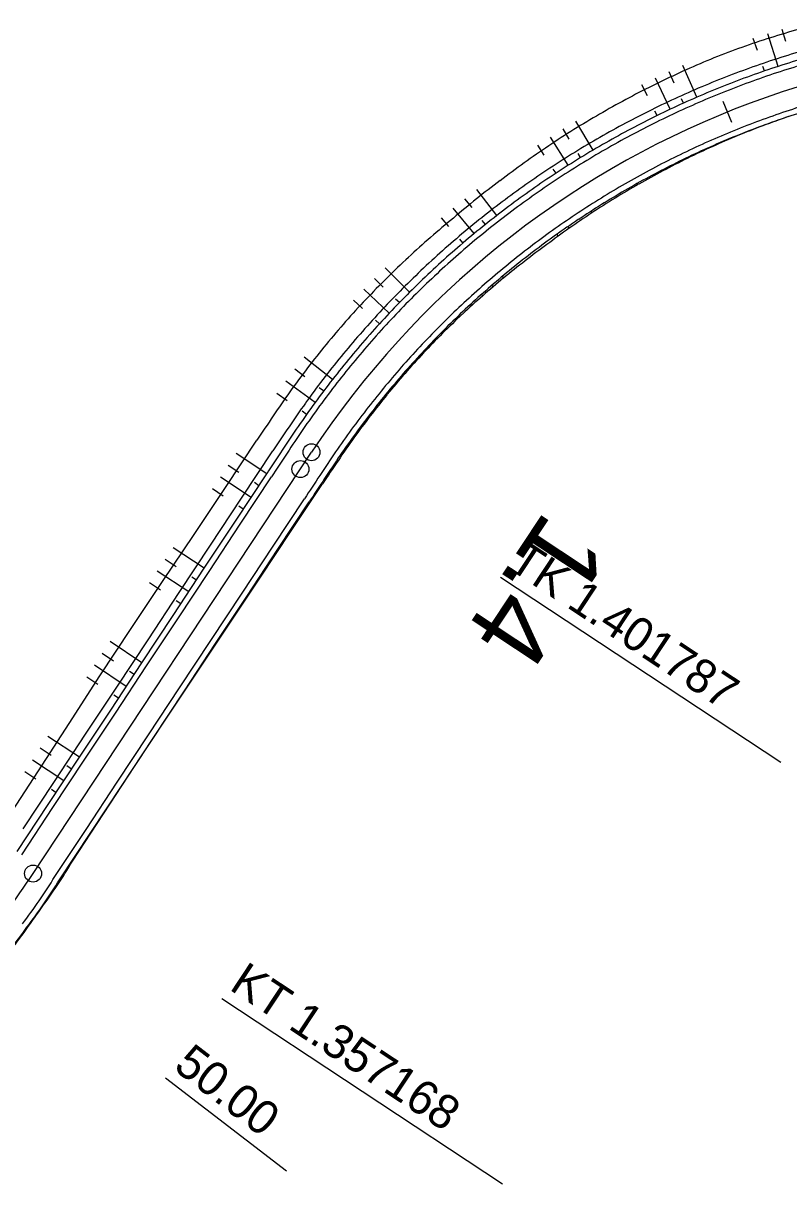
# Model space of a CAD drawing. Extents: x -481656 to -478728, y -1113199 to -1110710.
# Drawn here: x -478987.9 to -478920.3, y -1110817.8 to -1110715.2 of the extents above; entities that cross this region are included whole.
import ezdxf

# ---------------------------------------------------------------- set-up
doc = ezdxf.new("R2010")
doc.units = 0
for name, color, linetype in [('C5_HATCH_SLOPE_L', 7, 'Continuous'), ('C5_HATCH_SLOPE_R', 7, 'Continuous'), ('C5_HECTOMETRY', 7, 'Continuous'), ('C5_HLBODY', 7, 'Continuous'), ('C5_HRANA_TELESO', 7, 'Continuous'), ('C5_KORUNA', 7, 'Continuous'), ('C5_OSA', 7, 'Continuous'), ('C5_PRIKOP', 7, 'Continuous'), ('C5_STANICENI', 7, 'Continuous'), ('C5_ZPEVKRAJ', 7, 'Continuous')]:
    doc.layers.add(name, color=color, linetype=linetype)

msp = doc.modelspace()

# ---------------------------------------------------------------- linework, layer by layer
at = {"layer": 'C5_HATCH_SLOPE_L'}
for p, q in [((-478920.56, -1110716.84), (-478920.89, -1110715.79)), ((-478923.07, -1110717.64), (-478923.43, -1110716.58)), ((-478921.23, -1110719.05), (-478922.16, -1110716.18)), ((-478928.43, -1110721.78), (-478929.65, -1110718.97)), ((-478922.44, -1110719.45), (-478922.58, -1110719.07)), ((-478930.78, -1110722.84), (-478932.07, -1110720.09)), ((-478930.41, -1110720.53), (-478930.86, -1110719.52)), ((-478932.78, -1110721.66), (-478933.27, -1110720.68)), ((-478929.61, -1110722.3), (-478929.78, -1110721.92)), ((-478931.93, -1110723.39), (-478932.12, -1110723.02)), ((-478937.59, -1110726.45), (-478939.1, -1110723.88)), ((-478939.69, -1110725.48), (-478940.24, -1110724.58)), ((-478941.9, -1110726.89), (-478942.47, -1110726.02)), ((-478939.78, -1110727.79), (-478941.36, -1110725.29)), ((-478938.69, -1110727.11), (-478938.91, -1110726.74)), ((-478940.86, -1110728.49), (-478941.1, -1110728.12)), ((-478946.09, -1110732.22), (-478947.86, -1110729.92)), ((-478948.28, -1110731.53), (-478948.91, -1110730.74)), ((-478948.09, -1110733.82), (-478949.95, -1110731.58)), ((-478950.32, -1110733.2), (-478950.97, -1110732.43)), ((-478947.1, -1110733.01), (-478947.37, -1110732.66)), ((-478949.08, -1110734.65), (-478949.37, -1110734.31)), ((-478953.8, -1110739.01), (-478955.94, -1110736.86)), ((-478956.13, -1110738.54), (-478956.89, -1110737.79)), ((-478955.59, -1110740.85), (-478957.83, -1110738.74)), ((-478957.95, -1110740.43), (-478958.76, -1110739.7)), ((-478954.7, -1110739.92), (-478955.03, -1110739.6)), ((-478956.46, -1110741.79), (-478956.81, -1110741.48)), ((-478960.61, -1110746.7), (-478963.11, -1110744.75)), ((-478963.04, -1110746.48), (-478963.93, -1110745.8)), ((-478962.15, -1110748.75), (-478964.73, -1110746.87)), ((-478961.39, -1110747.72), (-478961.77, -1110747.44)), ((-478964.6, -1110748.6), (-478965.52, -1110747.95)), ((-478962.9, -1110749.8), (-478963.29, -1110749.52)), ((-478966.42, -1110755.05), (-478969.12, -1110753.26)), ((-478968.87, -1110754.93), (-478969.82, -1110754.3)), ((-478967.8, -1110757.14), (-478970.51, -1110755.34)), ((-478967.11, -1110756.09), (-478967.51, -1110755.82)), ((-478970.25, -1110757.01), (-478971.21, -1110756.38)), ((-478968.49, -1110758.18), (-478968.89, -1110757.91)), ((-478971.93, -1110763.39), (-478974.69, -1110761.57)), ((-478974.41, -1110763.25), (-478975.39, -1110762.61)), ((-478973.31, -1110765.48), (-478976.08, -1110763.65)), ((-478972.62, -1110764.44), (-478973.03, -1110764.17)), ((-478975.8, -1110765.33), (-478976.78, -1110764.68)), ((-478974, -1110766.52), (-478974.41, -1110766.25)), ((-478977.44, -1110771.74), (-478980.26, -1110769.87)), ((-478979.95, -1110771.58), (-478980.95, -1110770.92)), ((-478978.82, -1110773.82), (-478981.64, -1110771.96)), ((-478981.33, -1110773.66), (-478982.32, -1110773.01)), ((-478978.13, -1110772.78), (-478978.54, -1110772.51)), ((-478979.51, -1110774.86), (-478979.92, -1110774.59)), ((-478982.96, -1110780.08), (-478985.74, -1110778.24)), ((-478985.45, -1110779.93), (-478986.42, -1110779.29)), ((-478984.34, -1110782.16), (-478987.11, -1110780.33)), ((-478986.82, -1110782.02), (-478987.79, -1110781.38)), ((-478983.65, -1110781.12), (-478984.06, -1110780.85)), ((-478985.03, -1110783.21), (-478985.44, -1110782.93))]:
    msp.add_line(p, q, dxfattribs=at)
at = {"layer": 'C5_HATCH_SLOPE_R'}
for p, q in [((-478921.45, -1110723.87), (-478921.45, -1110723.88)), ((-478921.44, -1110723.89), (-478921.44, -1110723.89)), ((-478920.3, -1110723.48), (-478920.29, -1110723.49)), ((-478923.73, -1110724.71), (-478923.72, -1110724.73)), ((-478923.72, -1110724.74), (-478923.72, -1110724.74)), ((-478922.59, -1110724.28), (-478922.58, -1110724.3)), ((-478929.3, -1110727.12), (-478929.27, -1110727.19)), ((-478931.48, -1110728.2), (-478931.43, -1110728.29)), ((-478930.39, -1110727.65), (-478930.38, -1110727.69)), ((-478930.36, -1110727.73), (-478930.36, -1110727.73)), ((-478932.55, -1110728.77), (-478932.53, -1110728.82)), ((-478932.5, -1110728.86), (-478932.5, -1110728.86)), ((-478937.78, -1110731.85), (-478937.69, -1110731.99)), ((-478939.8, -1110733.2), (-478939.7, -1110733.36)), ((-478938.8, -1110732.52), (-478938.75, -1110732.59)), ((-478938.7, -1110732.67), (-478938.7, -1110732.67)), ((-478940.8, -1110733.9), (-478940.74, -1110733.98)), ((-478940.68, -1110734.06), (-478940.68, -1110734.06)), ((-478946.53, -1110738.4), (-478946.48, -1110738.46)), ((-478946.42, -1110738.53), (-478946.42, -1110738.53)), ((-478945.61, -1110737.61), (-478945.49, -1110737.75)), ((-478947.45, -1110739.2), (-478947.34, -1110739.32)), ((-478948.35, -1110740.01), (-478948.29, -1110740.07)), ((-478948.24, -1110740.13), (-478948.24, -1110740.13)), ((-478952.65, -1110744.29), (-478952.57, -1110744.37)), ((-478953.47, -1110745.19), (-478953.43, -1110745.23)), ((-478953.39, -1110745.27), (-478953.39, -1110745.27)), ((-478954.28, -1110746.1), (-478954.19, -1110746.17)), ((-478955.07, -1110747.02), (-478955.03, -1110747.06)), ((-478954.99, -1110747.09), (-478954.99, -1110747.09)), ((-478958.81, -1110751.81), (-478958.72, -1110751.87)), ((-478959.51, -1110752.8), (-478959.47, -1110752.83)), ((-478959.42, -1110752.86), (-478959.42, -1110752.86)), ((-478960.2, -1110753.8), (-478960.11, -1110753.86)), ((-478960.88, -1110754.82), (-478960.83, -1110754.85)), ((-478960.79, -1110754.88), (-478960.79, -1110754.88)), ((-478964.32, -1110760.04), (-478964.25, -1110760.09)), ((-478965.01, -1110761.08), (-478964.98, -1110761.11)), ((-478965.7, -1110762.12), (-478965.63, -1110762.17)), ((-478964.94, -1110761.13), (-478964.94, -1110761.13)), ((-478966.39, -1110763.17), (-478966.36, -1110763.19)), ((-478966.32, -1110763.21), (-478966.32, -1110763.21)), ((-478969.84, -1110768.38), (-478969.79, -1110768.42)), ((-478970.53, -1110769.43), (-478970.5, -1110769.44)), ((-478970.48, -1110769.45), (-478970.48, -1110769.45)), ((-478971.21, -1110770.47), (-478971.18, -1110770.49)), ((-478971.9, -1110771.51), (-478971.89, -1110771.52)), ((-478971.87, -1110771.53), (-478971.87, -1110771.53)), ((-478975.35, -1110776.73), (-478975.34, -1110776.73)), ((-478976.04, -1110777.77), (-478976.03, -1110777.77)), ((-478976.03, -1110777.77), (-478976.03, -1110777.77)), ((-478976.73, -1110778.81), (-478976.71, -1110778.82)), ((-478977.42, -1110779.85), (-478977.41, -1110779.86)), ((-478977.4, -1110779.86), (-478977.4, -1110779.86)), ((-478980.86, -1110785.07), (-478980.83, -1110785.09)), ((-478981.55, -1110786.11), (-478981.53, -1110786.12)), ((-478981.52, -1110786.13), (-478981.52, -1110786.13)), ((-478982.24, -1110787.16), (-478982.2, -1110787.18)), ((-478982.93, -1110788.2), (-478982.91, -1110788.21)), ((-478982.89, -1110788.22), (-478982.89, -1110788.22)), ((-478986.42, -1110793.44), (-478986.37, -1110793.47)), ((-478987.16, -1110794.49), (-478987.13, -1110794.5)), ((-478987.11, -1110794.52), (-478987.11, -1110794.52)), ((-478987.9, -1110795.52), (-478987.85, -1110795.56))]:
    msp.add_line(p, q, dxfattribs=at)
at = {"layer": 'C5_HECTOMETRY'}
msp.add_circle((-478963.44, -1110754.63), 0.75, dxfattribs=at)
at = {"layer": 'C5_HLBODY'}
for p, q in [((-478945.77, -1110764.16), (-478920.99, -1110780.53)), ((-478970.37, -1110801.39), (-478945.59, -1110817.76))]:
    msp.add_line(p, q, dxfattribs=at)
for centre in [(-478962.46, -1110753.14), (-478987.06, -1110790.36)]:
    msp.add_circle(centre, 0.75, dxfattribs=at)
at = {"layer": 'C5_HRANA_TELESO'}
for p, q in [((-478970.06, -1110756.25), (-478967.29, -1110752.08)), ((-478964.25, -1110760.09), (-478961.48, -1110755.92)), ((-478972.84, -1110760.41), (-478970.06, -1110756.25)), ((-478967.02, -1110764.25), (-478964.25, -1110760.09)), ((-478975.61, -1110764.56), (-478972.84, -1110760.41)), ((-478978.39, -1110768.72), (-478975.61, -1110764.56)), ((-478969.79, -1110768.42), (-478967.02, -1110764.25)), ((-478981.15, -1110772.89), (-478978.39, -1110768.72)), ((-478972.57, -1110772.57), (-478969.79, -1110768.42)), ((-478983.87, -1110777.09), (-478981.15, -1110772.89)), ((-478975.34, -1110776.73), (-478972.57, -1110772.57)), ((-478986.59, -1110781.28), (-478983.87, -1110777.09)), ((-478978.09, -1110780.91), (-478975.34, -1110776.73)), ((-478989.32, -1110785.48), (-478986.59, -1110781.28)), ((-478980.83, -1110785.09), (-478978.09, -1110780.91)), ((-478983.58, -1110789.27), (-478980.83, -1110785.09))]:
    msp.add_line(p, q, dxfattribs=at)
for centre, radius, start, end in [((-478896.21, -1110797.39), 84.85, 104.504, 108.0851), ((-478895.81, -1110797.27), 84.87, 108.3674, 111.9484), ((-478894.52, -1110796.7), 84.83, 112.897, 116.4784), ((-478894.53, -1110796.61), 84.75, 116.5022, 120.0836), ((-478894.54, -1110796.52), 84.67, 120.1042, 123.6856), ((-478895.32, -1110797.09), 77.73, 108.7397, 112.3208), ((-478895.17, -1110797), 77.7, 112.4513, 116.0324), ((-478894.55, -1110796.43), 84.58, 123.7165, 127.298), ((-478895.07, -1110796.9), 77.65, 116.1284, 119.7096), ((-478894.99, -1110796.67), 84.51, 126.9602, 130.5414), ((-478895.07, -1110796.85), 77.61, 119.73, 123.3111), ((-478895.07, -1110796.79), 77.56, 123.3359, 126.917), ((-478896.37, -1110797.82), 84.51, 129.3279, 132.9091), ((-478896.14, -1110797.57), 77.55, 125.9385, 129.5196), ((-478896.39, -1110797.92), 84.56, 132.8479, 136.4291), ((-478896.11, -1110797.59), 77.59, 129.5275, 133.1086), ((-478895.92, -1110797.47), 84.6, 136.8741, 140.4551), ((-478896.08, -1110797.6), 77.62, 133.1216, 136.7027), ((-478895.76, -1110797.3), 84.61, 140.6128, 144.1938), ((-478895.8, -1110797.33), 77.64, 136.9881, 140.5691), ((-478755.88, -1110892.6), 253.85, 145.2193, 146.3896), ((-478895.71, -1110797.24), 77.64, 140.666, 144.247), ((-478767.54, -1110884.93), 232.93, 145.1618, 146.3683), ((-479027.52, -1110763.08), 51.15, 323.5502, 329.2088), ((-479070.67, -1110735.48), 102.31, 322.6103, 325.4751)]:
    msp.add_arc(centre, radius, start, end, dxfattribs=at)
at = {"layer": 'C5_KORUNA'}
for p, q in [((-478969.17, -1110759.22), (-478966.42, -1110755.05)), ((-478965.42, -1110761.7), (-478962.66, -1110757.53)), ((-478971.93, -1110763.39), (-478969.17, -1110759.22)), ((-478968.18, -1110765.87), (-478965.42, -1110761.7)), ((-478974.69, -1110767.56), (-478971.93, -1110763.39)), ((-478970.93, -1110770.04), (-478968.18, -1110765.87)), ((-478977.44, -1110771.74), (-478974.69, -1110767.56)), ((-478973.69, -1110774.22), (-478970.93, -1110770.04)), ((-478980.2, -1110775.91), (-478977.44, -1110771.74)), ((-478976.45, -1110778.39), (-478973.69, -1110774.22)), ((-478982.96, -1110780.08), (-478980.2, -1110775.91)), ((-478979.2, -1110782.56), (-478976.45, -1110778.39)), ((-478985.71, -1110784.25), (-478982.96, -1110780.08)), ((-478981.96, -1110786.73), (-478979.2, -1110782.56)), ((-478988.47, -1110788.42), (-478985.71, -1110784.25)), ((-478984.72, -1110790.9), (-478981.96, -1110786.73))]:
    msp.add_line(p, q, dxfattribs=at)
for centre, radius, start, end in [((-478895.71, -1110797.24), 82.25, 106.2794, 109.8604), ((-478895.71, -1110797.24), 82.25, 109.8604, 113.4414), ((-478895.71, -1110797.24), 82.25, 113.4414, 117.0224), ((-478895.71, -1110797.24), 77.75, 106.2794, 109.8604), ((-478895.71, -1110797.24), 82.25, 117.0224, 120.6034), ((-478895.71, -1110797.24), 77.75, 109.8604, 113.4414), ((-478895.71, -1110797.24), 77.75, 113.4414, 117.0224), ((-478895.71, -1110797.24), 82.25, 120.6034, 124.1843), ((-478895.71, -1110797.24), 77.75, 117.0224, 120.6034), ((-478895.71, -1110797.24), 82.25, 124.1843, 127.7653), ((-478895.71, -1110797.24), 77.75, 120.6034, 124.1843), ((-478895.71, -1110797.24), 82.25, 127.7653, 131.3463), ((-478895.71, -1110797.24), 77.75, 124.1843, 127.7653), ((-478895.71, -1110797.24), 82.25, 131.3463, 134.9273), ((-478895.71, -1110797.24), 77.75, 127.7653, 131.3463), ((-478895.71, -1110797.24), 82.25, 134.9273, 138.5083), ((-478895.71, -1110797.24), 77.75, 131.3463, 134.9273), ((-478895.71, -1110797.24), 77.75, 134.9273, 138.5083), ((-478895.71, -1110797.24), 82.25, 138.5083, 142.0893), ((-478895.71, -1110797.24), 77.75, 138.5083, 142.0893), ((-478895.71, -1110797.24), 82.25, 142.0893, 145.6703), ((-478895.71, -1110797.24), 77.75, 142.0893, 145.6703), ((-478759.43, -1110889.36), 246.75, 145.8514, 147.0204), ((-478766.93, -1110884.39), 233.25, 145.8305, 147.0503), ((-479028.26, -1110764.12), 51.12, 322.6945, 328.4048), ((-479070.49, -1110735.23), 102.25, 321.2966, 324.1614)]:
    msp.add_arc(centre, radius, start, end, dxfattribs=at)
at = {"layer": 'C5_OSA'}
msp.add_line((-478987.06, -1110790.36), (-478962.46, -1110753.14), dxfattribs=at)
for centre, radius, start, end in [((-478895.71, -1110797.24), 80, 76.6017, 146.545), ((-479070.49, -1110735.23), 100, 317.0793, 326.545)]:
    msp.add_arc(centre, radius, start, end, dxfattribs=at)
at = {"layer": 'C5_PRIKOP'}
for p, q in [((-478968.63, -1110757.19), (-478965.88, -1110753.02)), ((-478971.39, -1110761.36), (-478968.63, -1110757.19)), ((-478974.15, -1110765.53), (-478971.39, -1110761.36)), ((-478976.9, -1110769.71), (-478974.15, -1110765.53)), ((-478979.66, -1110773.88), (-478976.9, -1110769.71)), ((-478982.42, -1110778.05), (-478979.66, -1110773.88)), ((-478985.17, -1110782.22), (-478982.42, -1110778.05)), ((-478987.93, -1110786.39), (-478985.17, -1110782.22))]:
    msp.add_line(p, q, dxfattribs=at)
for centre, radius, start, end in [((-478895.71, -1110797.24), 82.92, 104.8528, 108.4338), ((-478895.71, -1110797.24), 82.92, 108.4338, 112.0148), ((-478895.71, -1110797.24), 82.92, 112.0148, 115.5957), ((-478895.71, -1110797.24), 82.92, 115.5957, 119.1767), ((-478895.71, -1110797.24), 82.92, 119.1767, 122.7577), ((-478895.71, -1110797.24), 82.92, 122.7577, 126.3387), ((-478895.71, -1110797.24), 82.92, 126.3387, 129.9197), ((-478895.71, -1110797.24), 82.92, 129.9197, 133.5007), ((-478895.71, -1110797.24), 82.92, 133.5007, 137.0817), ((-478895.71, -1110797.24), 82.92, 137.0817, 140.6626), ((-478895.71, -1110797.24), 82.92, 140.6626, 144.2436), ((-478758.72, -1110890.73), 248.75, 145.2068, 146.3854)]:
    msp.add_arc(centre, radius, start, end, dxfattribs=at)
at = {"layer": 'C5_STANICENI'}
for p, q in [((-478925.33, -1110724), (-478926.08, -1110722.15)), ((-478975.36, -1110808.39), (-478964.66, -1110816.62))]:
    msp.add_line(p, q, dxfattribs=at)
at = {"layer": 'C5_ZPEVKRAJ'}
for p, q in [((-478968.76, -1110759.5), (-478966, -1110755.32)), ((-478965.84, -1110761.43), (-478963.08, -1110757.25)), ((-478971.51, -1110763.67), (-478968.76, -1110759.5)), ((-478968.59, -1110765.6), (-478965.84, -1110761.43)), ((-478974.27, -1110767.84), (-478971.51, -1110763.67)), ((-478971.35, -1110769.77), (-478968.59, -1110765.6)), ((-478977.03, -1110772.01), (-478974.27, -1110767.84)), ((-478974.11, -1110773.94), (-478971.35, -1110769.77)), ((-478979.78, -1110776.18), (-478977.03, -1110772.01)), ((-478976.86, -1110778.11), (-478974.11, -1110773.94)), ((-478982.54, -1110780.35), (-478979.78, -1110776.18)), ((-478979.62, -1110782.28), (-478976.86, -1110778.11)), ((-478985.3, -1110784.53), (-478982.54, -1110780.35)), ((-478982.38, -1110786.46), (-478979.62, -1110782.28)), ((-478988.05, -1110788.7), (-478985.3, -1110784.53)), ((-478985.13, -1110790.63), (-478982.38, -1110786.46))]:
    msp.add_line(p, q, dxfattribs=at)
for centre, radius, start, end in [((-478895.71, -1110797.24), 81.75, 106.2794, 109.8604), ((-478895.71, -1110797.24), 81.75, 109.8604, 113.4414), ((-478895.71, -1110797.24), 78.25, 106.2794, 109.8604), ((-478895.71, -1110797.24), 81.75, 113.4414, 117.0224), ((-478895.71, -1110797.24), 78.25, 109.8604, 113.4414), ((-478895.71, -1110797.24), 81.75, 117.0224, 120.6034), ((-478895.71, -1110797.24), 78.25, 113.4414, 117.0224), ((-478895.71, -1110797.24), 81.75, 120.6034, 124.1843), ((-478895.71, -1110797.24), 78.25, 117.0224, 120.6034), ((-478895.71, -1110797.24), 81.75, 124.1843, 127.7653), ((-478895.71, -1110797.24), 78.25, 120.6034, 124.1843), ((-478895.71, -1110797.24), 81.75, 127.7653, 131.3463), ((-478895.71, -1110797.24), 78.25, 124.1843, 127.7653), ((-478895.71, -1110797.24), 78.25, 127.7653, 131.3463), ((-478895.71, -1110797.24), 81.75, 131.3463, 134.9273), ((-478895.71, -1110797.24), 78.25, 131.3463, 134.9273), ((-478895.71, -1110797.24), 81.75, 134.9273, 138.5083), ((-478895.71, -1110797.24), 78.25, 134.9273, 138.5083), ((-478895.71, -1110797.24), 81.75, 138.5083, 142.0893), ((-478895.71, -1110797.24), 78.25, 138.5083, 142.0893), ((-478895.71, -1110797.24), 81.75, 142.0893, 145.6703), ((-478895.71, -1110797.24), 78.25, 142.0893, 145.6703), ((-478760.26, -1110888.81), 245.25, 145.8492, 147.0236), ((-478766.1, -1110884.95), 234.75, 145.833, 147.0468), ((-479028.47, -1110763.97), 50.88, 322.693, 328.4079)]:
    msp.add_arc(centre, radius, start, end, dxfattribs=at)

# ---------------------------------------------------------------- texts
at = {"layer": 'C5_HECTOMETRY'}
msp.add_text('1.4', height=6.999, rotation=236.4993, dxfattribs=at).set_placement((-478941.77, -1110758.11))
at = {"layer": 'C5_HLBODY'}
for s, p in [('TK 1.401787', (-478945.22, -1110763.33)), ('KT 1.357168', (-478969.82, -1110800.55))]:
    msp.add_text(s, height=2.999, rotation=326.545, dxfattribs=at).set_placement(p)
at = {"layer": 'C5_STANICENI'}
msp.add_text('50.00', height=3, rotation=322.4379, dxfattribs=at).set_placement((-478974.76, -1110807.6))

doc.saveas('drawing.dxf')
